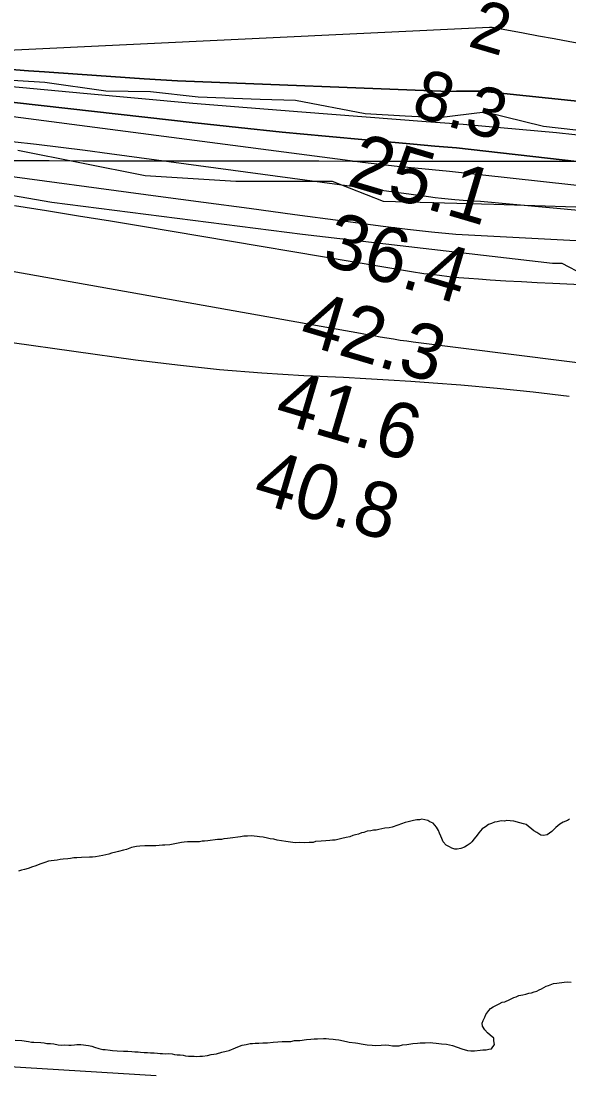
# Model space of a CAD drawing. Extents: x 3219052 to 3256913, y 800770 to 826146.
# Drawn here: x 3234446 to 3235111, y 811124 to 812399 of the extents above; entities that cross this region are included whole.
import ezdxf

# ---------------------------------------------------------------- set-up
doc = ezdxf.new("R2010")
doc.units = 0
for name, color, linetype in [('V-GRID-MAJR', 7, 'Continuous'), ('V-LEVE-TOET', 7, 'Continuous'), ('V-RIVR-EDGE', 7, 'Continuous'), ('V-RIVR-RANG', 7, 'Continuous'), ('V-SITE-VEGE', 7, 'Continuous'), ('V-TOPO-DPTH', 7, 'Continuous'), ('V-TOPO-MAJR', 7, 'Continuous'), ('V-TOPO-MINR', 7, 'Continuous'), ('V-TOPO-SHOR', 7, 'Continuous'), ('V-TOPO-WATR', 7, 'Continuous')]:
    doc.layers.add(name, color=color, linetype=linetype)

msp = doc.modelspace()

# ---------------------------------------------------------------- linework, layer by layer
at = {"layer": 'V-GRID-MAJR'}
msp.add_spline([(3223229.222, 812245.659), (3228465.955, 812237.661), (3233702.6890000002, 812230.425), (3238939.4250000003, 812223.951), (3244176.161, 812218.238), (3249412.899, 812213.287), (3254649.637, 812209.098), (3254649.6380000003, 812209.098)], degree=3, dxfattribs=at)
at = {"layer": 'V-LEVE-TOET'}
msp.add_lwpolyline([(3234610.1010000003, 811119.314), (3234425.474, 811130.638), (3234187.478, 811141.719), (3233931.83, 811153.87), (3233761.803, 811162.105), (3233604.955, 811165.837), (3233406.5160000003, 811173.3470000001), (3233168.7090000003, 811179.556), (3232928.452, 811181.5160000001)], dxfattribs=at)
at = {"layer": 'V-RIVR-EDGE'}
msp.add_lwpolyline([(3234389.041930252, 812329.7287057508), (3234474.661383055, 812324.7355224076), (3234548.96527335, 812314.1194897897), (3234602.86301311, 812313.116857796), (3234661.094620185, 812306.8873591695), (3234736.287210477, 812304.0933543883), (3234778.8822856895, 812302.6839914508), (3234863.604439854, 812286.3913680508), (3234912.281761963, 812283.6629279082), (3234953.1370562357, 812281.8231877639), (3235009.2275255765, 812288.6393591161), (3235080.036806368, 812271.0771006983), (3235140.8753977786, 812264.406476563)], dxfattribs=at)
at = {"layer": 'V-SITE-VEGE'}
for points in [[(3234442.042, 812242.192), (3234596.775, 812211.224), (3234706.808, 812204.34), (3234823.718, 812204.34), (3234885.61, 812180.2540000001), (3235019.714, 812176.811), (3235119.429, 812173.371), (3235301.6720000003, 812152.725), (3235432.3340000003, 812142.4010000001), (3235559.558, 812135.519), (3235648.9590000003, 812111.431), (3235732.2430000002, 812115.209)], [(3235260.409, 812021.964), (3235102.8910000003, 812104.5800000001), (3235091.0130000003, 812104.816), (3234787.737, 812139.888), (3234483.434, 812178.7220000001), (3234217.1350000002, 812224.724)]]:
    msp.add_lwpolyline(points, dxfattribs=at)
at = {"layer": 'V-TOPO-DPTH'}
for points in [[(3236219.5797993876, 812171.8300673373), (3235701.0112393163, 812242.9258117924), (3235694.414456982, 812243.1129452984), (3235660.3686561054, 812245.4549364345), (3235642.6340134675, 812246.8566528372), (3235624.924136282, 812248.4987800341), (3235607.251407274, 812250.501523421), (3235589.6034437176, 812252.7446776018), (3235004.7512205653, 812313.4886094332), (3234994.697642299, 812313.8248193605), (3234984.6384474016, 812313.833251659), (3234974.575508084, 812313.6231655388), (3234965.4019531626, 812313.2819710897), (3234635.619298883, 812326.130380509), (3234595.28107196, 812328.6473075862), (3234554.9512253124, 812331.287867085), (3234514.633949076, 812334.1138752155), (3234474.3250531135, 812337.0635157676), (3234455.097546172, 812338.5149646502), (3234424.4038720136, 812340.7604837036)], [(3234424.4038720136, 812340.7604837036), (3234455.097546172, 812338.5149646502), (3234474.3250531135, 812337.0635157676), (3234514.633949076, 812334.1138752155), (3234554.9512253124, 812331.287867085), (3234595.28107196, 812328.6473075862), (3234635.619298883, 812326.130380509), (3234965.4019531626, 812313.2819710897), (3234974.575508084, 812313.6231655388), (3234984.6384474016, 812313.833251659), (3234994.697642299, 812313.8248193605), (3235004.7512205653, 812313.4886094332), (3235589.6034437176, 812252.7446776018), (3235607.251407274, 812250.501523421), (3235624.924136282, 812248.4987800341), (3235642.6340134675, 812246.8566528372), (3235660.3686561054, 812245.4549364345), (3235694.414456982, 812243.1129452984), (3235701.0112393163, 812242.9258117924), (3236219.5797993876, 812171.8300673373)], [(3237711.6959470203, 812013.2851889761), (3236978.4446943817, 812069.2369252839), (3236972.67980126, 812070.7520773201), (3235637.6560567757, 812168.0903933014), (3235630.8095992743, 812168.954961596), (3235623.973784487, 812169.9111963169), (3235617.340974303, 812170.906967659), (3235607.1922265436, 812172.3974644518), (3235597.0374562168, 812173.8447153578), (3235586.873652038, 812175.2270974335), (3235576.7038252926, 812176.5662336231), (3234974.3108995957, 812244.8412438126), (3234948.2321198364, 812247.113933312), (3234922.1547592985, 812249.4029973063), (3234868.502054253, 812254.1380784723), (3234815.6183309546, 812258.9957155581), (3234762.7598384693, 812264.104991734), (3234709.9391922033, 812269.5917265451), (3234657.143776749, 812275.3301004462), (3234408.9824128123, 812303.2001529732)]]:
    msp.add_lwpolyline(points, dxfattribs=at)
at = {"layer": 'V-TOPO-MAJR'}
msp.add_lwpolyline([(3234402.0279410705, 812214.723163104), (3234612.1876691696, 812186.4229055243), (3234667.5159077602, 812178.9879433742), (3234722.846874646, 812171.5733839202), (3234778.1819339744, 812164.1894285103), (3234833.519721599, 812156.8258757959), (3234885.3669442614, 812149.9413883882), (3234914.810493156, 812146.3028173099), (3234944.2904495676, 812143.0205567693), (3234973.825017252, 812140.2727620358), (3235558.23428724, 812109.4964151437), (3235565.037816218, 812108.1963231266), (3235571.830206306, 812106.8420574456), (3235578.6058880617, 812105.4065312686), (3235585.3704309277, 812103.9168314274), (3236210.408453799, 812045.0384253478)], dxfattribs=at)
at = {"layer": 'V-TOPO-MINR'}
for points in [[(3234430.0256441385, 812363.2484721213), (3235014.625049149, 812391.2791421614), (3235015.10351626, 812391.3047767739), (3235016.9311097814, 812391.3300911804), (3235017.4268970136, 812391.2858917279), (3235017.5909552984, 812391.2598474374), (3235055.2225959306, 812384.4319179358), (3235074.202504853, 812380.9905720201), (3235093.182972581, 812377.5523130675), (3235112.1642785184, 812374.118684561), (3235634.783277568, 812279.7305905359), (3235637.677363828, 812279.3185897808), (3235642.425527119, 812279.2395690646), (3235643.48957829, 812279.4625913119), (3236265.9415057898, 812233.7821427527), (3236282.6928479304, 812233.3282800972), (3236299.492951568, 812233.657322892), (3236328.688809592, 812235.2577443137), (3236330.8262788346, 812235.612818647), (3237034.8478958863, 812152.3173607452), (3237042.4332785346, 812150.4810922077), (3237070.4625623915, 812144.2142284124), (3238468.788826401, 811995.0523872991)], [(3234430.7351166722, 812319.5894952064), (3234521.8584367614, 812311.0818811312), (3234588.0440022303, 812305.0715375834), (3234654.248536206, 812299.284727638), (3234720.4815229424, 812293.8332180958), (3234786.7334781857, 812288.6052421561), (3234937.545494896, 812277.088712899), (3234960.1515100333, 812275.3270871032), (3234982.753703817, 812273.5186181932), (3235005.3501655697, 812271.6398846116), (3235027.942805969, 812269.7143079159), (3235050.5264560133, 812267.68998244), (3235073.1019409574, 812265.5808423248), (3235095.6651782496, 812263.3444802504), (3235118.2202504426, 812261.0233035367), (3235177.6233829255, 812254.7407870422), (3235229.882634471, 812249.3019893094), (3235282.1535355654, 812243.9795257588), (3235334.441910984, 812238.8315634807), (3235386.7419359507, 812233.7999353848), (3235444.531425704, 812228.3375060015), (3235472.3495647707, 812225.6913983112), (3235500.165579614, 812223.0232822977), (3236254.4273411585, 812139.8911612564)], [(3234408.9824128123, 812303.2001529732), (3234657.143776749, 812275.3301004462), (3234709.9391922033, 812269.5917265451), (3234762.7598384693, 812264.104991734), (3234815.6183309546, 812258.9957155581), (3234868.502054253, 812254.1380784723), (3234922.1547592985, 812249.4029973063), (3234948.2321198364, 812247.113933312), (3234974.3108995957, 812244.8412438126), (3235576.7038252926, 812176.5662336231), (3235586.873652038, 812175.2270974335), (3235597.0374562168, 812173.8447153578), (3235607.1922265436, 812172.3974644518), (3235617.340974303, 812170.906967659), (3235623.973784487, 812169.9111963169), (3235630.8095992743, 812168.954961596), (3235637.6560567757, 812168.0903933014), (3236972.67980126, 812070.7520773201), (3236978.4446943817, 812069.2369252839), (3237711.6959470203, 812013.2851889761)], [(3234389.5547021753, 812289.0833983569), (3234839.3901921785, 812230.3752246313), (3234860.4491929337, 812227.7203740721), (3234881.522412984, 812225.188400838), (3234902.6169619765, 812222.8407435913), (3234923.7257302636, 812220.6159636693), (3234944.851145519, 812218.5494723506), (3234965.9845341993, 812216.5711254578), (3235558.795259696, 812151.487020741), (3235587.044893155, 812147.1051769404), (3235615.253882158, 812142.4688761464), (3235643.435774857, 812137.662937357), (3236942.230676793, 812058.3951681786), (3237652.881814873, 811987.293061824)], [(3234434.962991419, 812252.6385372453), (3234464.5223465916, 812249.2440999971), (3234494.0648566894, 812245.7127790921), (3234523.582099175, 812241.9761327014), (3234553.0824965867, 812238.1026026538), (3234940.5309824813, 812185.8580709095), (3234948.4701514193, 812184.853397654), (3234956.4185995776, 812183.9352381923), (3234964.3809665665, 812183.1468494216), (3234972.352612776, 812182.4449744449), (3234987.958356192, 812181.1991342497), (3235003.746365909, 812180.0591836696), (3235545.818580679, 812130.5743479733), (3235562.250964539, 812127.8017561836), (3235578.6617078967, 812124.9101439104), (3236207.163922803, 812094.8384156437), (3236213.1819288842, 812092.9794959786), (3236920.467636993, 812041.1775389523), (3236943.0259246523, 812035.7495556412), (3238400.420479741, 811879.8452404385)], [(3234438.055331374, 812174.9907826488), (3234476.8515582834, 812168.8569196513), (3234515.633267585, 812162.6335782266), (3234554.393200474, 812156.276019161), (3234593.138615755, 812149.8289816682), (3234919.659744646, 812094.9165510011), (3234924.761084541, 812094.0968699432), (3234929.86955215, 812093.3269420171), (3234934.9887113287, 812092.6316437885), (3234940.11499822, 812091.9860986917), (3234953.649429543, 812090.3819703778), (3234965.556697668, 812089.0622577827), (3234977.475182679, 812087.8632320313), (3234989.410493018, 812086.8452365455), (3235001.357020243, 812085.9479279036), (3235015.4173163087, 812084.999109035), (3235034.405919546, 812083.7800412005), (3235053.399203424, 812082.6437476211), (3235072.399508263, 812081.6316154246), (3235091.4044937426, 812080.7022574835), (3235218.983054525, 812074.8814288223)], [(3234368.599802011, 812107.1565972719), (3234858.0144645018, 812020.0166565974), (3234865.9983301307, 812018.6020717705), (3234873.9837667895, 812017.1964563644), (3234881.971559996, 812015.8042950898), (3234889.9609242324, 812014.4211032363), (3234897.9595660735, 812013.098958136), (3234905.969002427, 812011.8492084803), (3234913.9946305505, 812010.7080519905), (3234922.0310531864, 812009.6392909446), (3235285.225404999, 811963.8392559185), (3235322.5443838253, 811959.3574029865), (3235359.894653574, 811955.1704357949)], [(3235111.398821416, 811943.197295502), (3235067.643614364, 811948.6571665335), (3235023.776314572, 811953.1279992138), (3234979.8342862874, 811956.9394729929), (3234946.2612483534, 811959.4700492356), (3234919.0427629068, 811961.4098859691), (3234891.815127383, 811963.2014173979), (3234864.5737667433, 811964.7704908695), (3234837.323256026, 811966.1912590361), (3234789.247706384, 811968.5009455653), (3234738.016922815, 811971.6556376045), (3234686.871815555, 811975.7292158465), (3234635.8552227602, 811981.1811233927), (3234584.9243062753, 811987.5519171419), (3234359.9949945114, 812018.7758344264)]]:
    msp.add_lwpolyline(points, dxfattribs=at)
at = {"layer": 'V-TOPO-SHOR'}
for points in [[(3235111.613, 811430.702), (3235109.0700000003, 811428.937), (3235103.954, 811427.122), (3235099.71, 811424.464), (3235095.0640000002, 811420.514), (3235092.108, 811417.882), (3235090.003, 811415.6950000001), (3235084.498, 811411.726), (3235080.222, 811410.786), (3235076.779, 811411.15), (3235071.995, 811414.4940000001), (3235068.519, 811416.573), (3235065.904, 811418.67), (3235061.548, 811422.023), (3235058.933, 811424.12), (3235055.912, 811424.921), (3235051.167, 811426.1190000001), (3235044.259, 811428.134), (3235039.5300000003, 811428.4720000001), (3235035.659, 811428.828), (3235032.663, 811428.343), (3235028.792, 811428.697), (3235023.666, 811427.313), (3235020.6720000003, 811426.828), (3235016.832, 811425.466), (3235013.424, 811424.1140000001), (3235009.611, 811421.466), (3235005.7970000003, 811418.816), (3235003.6920000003, 811416.631), (3235001.595, 811414.013), (3234999.498, 811411.398), (3234995.725, 811406.604), (3234993.217, 811403.122), (3234991.111, 811400.935), (3234987.29, 811398.7170000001), (3234984.326, 811396.513), (3234979.628, 811395.135), (3234975.3540000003, 811394.197), (3234972.349, 811394.137), (3234968.892, 811395.36), (3234965.855, 811397.0210000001), (3234961.952, 811399.093), (3234958.437, 811403.319), (3234956.647, 811407.148), (3234955.304, 811410.128), (3234953.95, 811413.536), (3234952.596, 811416.946), (3234950.378, 811420.767), (3234945.988, 811425.836), (3234942.092, 811427.479), (3234939.485, 811429.148), (3234936.036, 811429.9400000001), (3234932.585, 811430.733), (3234929.597, 811429.818), (3234926.165, 811429.752), (3234922.319, 811428.8200000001), (3234915.907, 811427.411), (3234912.06, 811426.479), (3234907.792, 811425.109), (3234903.105, 811423.305), (3234896.279, 811421.028), (3234892.862, 811420.104), (3234887.292, 811419.567), (3234880.019, 811418.142), (3234877.031, 811417.226), (3234873.599, 811417.161), (3234870.603, 811416.676), (3234865.89, 811416.155), (3234862.061, 811414.365), (3234859.0640000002, 811413.88), (3234855.654, 811412.5260000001), (3234851.808, 811411.594), (3234848.8200000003, 811410.679), (3234844.982, 811409.319), (3234840.708, 811408.3790000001), (3234835.154, 811406.986), (3234832.1580000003, 811406.4990000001), (3234827.032, 811405.115), (3234824.0270000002, 811405.057), (3234820.603, 811404.562), (3234815.88, 811404.474), (3234810.31, 811403.937), (3234803.453, 811403.378), (3234800.465, 811402.462), (3234795.742, 811402.372), (3234790.1720000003, 811401.838)], [(3234790.1720000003, 811401.838), (3234783.727, 811402.145), (3234779.006, 811402.055), (3234775.9930000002, 811402.426), (3234772.981, 811402.7980000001), (3234767.386, 811403.552), (3234756.623, 811405.063), (3234752.736, 811406.278), (3234748.437, 811406.6240000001), (3234744.989, 811407.419), (3234739.813, 811408.608), (3234735.504, 811409.385), (3234732.494, 811409.755), (3234729.051, 811410.12), (3234725.61, 811410.484), (3234720.898, 811409.964), (3234716.177, 811409.8740000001), (3234712.321, 811409.372), (3234699.9080000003, 811407.421), (3234696.4760000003, 811407.353), (3234692.193, 811406.843), (3234689.205, 811405.9280000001), (3234684.485, 811405.838), (3234672.492, 811404.322), (3234668.637, 811403.8200000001), (3234665.633, 811403.763), (3234662.637, 811403.2760000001), (3234658.774, 811403.204), (3234651.4790000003, 811403.0650000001), (3234648.0470000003, 811402.9990000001), (3234643.754, 811402.917), (3234640.758, 811402.432), (3234634.773, 811401.029), (3234626.645, 811399.587), (3234620.644, 811399.042), (3234617.64, 811398.987), (3234609.495, 811398.4010000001), (3234603.486, 811398.289), (3234599.196, 811398.207), (3234596.1890000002, 811398.149), (3234590.182, 811398.035), (3234585.9, 811397.525), (3234579.916, 811396.1240000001), (3234573.948, 811393.863), (3234570.102, 811392.931), (3234564.117, 811391.528), (3234561.129, 811390.615), (3234555.575, 811389.22), (3234552.5870000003, 811388.305), (3234548.741, 811387.373), (3234545.323, 811386.449), (3234536.336, 811384.991), (3234532.482, 811384.487), (3234529.048, 811384.422), (3234519.178, 811384.235), (3234513.608, 811383.701), (3234510.173, 811383.633), (3234505.8910000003, 811383.123), (3234502.895, 811382.638), (3234496.894, 811382.093), (3234493.47, 811381.599), (3234489.613, 811381.098), (3234482.335, 811380.1), (3234479.338, 811379.615), (3234474.642, 811378.237), (3234469.955, 811376.43), (3234462.7090000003, 811373.7170000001), (3234459.721, 811372.801), (3234454.603, 811370.987), (3234449.907, 811369.608), (3234446.489, 811368.685), (3234442.642, 811367.755)], [(3234682.983, 811146.071), (3234689.818, 811147.919), (3234694.9420000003, 811149.305), (3234698.36, 811150.229), (3234706.028, 811153.3790000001), (3234711.143, 811155.193), (3234714.123, 811156.539), (3234719.258, 811157.495), (3234723.9620000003, 811158.443), (3234726.966, 811158.501), (3234729.9620000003, 811158.986), (3234734.683, 811159.076), (3234739.404, 811159.166), (3234744.983, 811159.273), (3234751.833, 811160.26), (3234757.412, 811160.366), (3234762.982, 811160.903), (3234770.279, 811161.04), (3234773.284, 811161.0970000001), (3234777.988, 811162.046), (3234780.9930000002, 811162.103), (3234784.4250000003, 811162.169), (3234792.5640000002, 811163.18), (3234797.704, 811163.709), (3234801.559, 811164.21), (3234805.8510000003, 811164.292), (3234813.146, 811164.432), (3234816.151, 811164.4890000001), (3234819.591, 811164.1240000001), (3234824.75, 811163.7930000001), (3234827.7630000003, 811163.422), (3234831.633, 811163.066), (3234841.116, 811161.1), (3234844.136, 811160.299), (3234851.886, 811159.158), (3234854.899, 811158.785), (3234858.778, 811158.001), (3234866.097, 811156.8520000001), (3234872.112, 811156.537), (3234876.413, 811156.188), (3234882.852, 811156.311), (3234888.85, 811156.854), (3234892.291, 811156.492), (3234896.6, 811155.713), (3234904.753, 811155.8690000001), (3234909.029, 811156.809), (3234914.1720000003, 811157.335), (3234921.45, 811158.333), (3234927.021, 811158.8690000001), (3234930.447, 811159.363), (3234933.452, 811159.42), (3234936.454, 811159.4770000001), (3234942.465, 811159.59), (3234945.906, 811159.228), (3234949.776, 811158.871), (3234956.23, 811158.136), (3234962.247, 811157.821), (3234966.126, 811157.036), (3234969.574, 811156.2440000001), (3234975.194, 811154.204), (3234980.8140000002, 811152.164), (3234987.722, 811150.149), (3234992.02, 811149.801), (3234996.321, 811149.453), (3235003.1720000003, 811150.442), (3235006.596, 811150.935), (3235010.4590000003, 811151.009), (3235013.8850000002, 811151.505), (3235016.879, 811151.99), (3235020.645, 811157.214), (3235019.697, 811161.919), (3235019.64, 811164.9230000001), (3235015.276, 811168.704), (3235012.214, 811171.6510000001), (3235008.716, 811175.02), (3235006.049, 811179.689), (3235005.556, 811183.116), (3235006.778, 811186.573), (3235008.8510000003, 811190.476), (3235010.082, 811193.505), (3235013.846, 811198.729), (3235015.949, 811200.915), (3235018.913, 811203.118), (3235026.144, 811206.6900000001), (3235029.974, 811208.48), (3235032.97, 811208.9670000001), (3235039.35, 811212.093), (3235044.029, 811214.329), (3235047.017, 811215.245), (3235049.997, 811216.588), (3235055.132, 811217.544), (3235058.548, 811218.468), (3235062.394, 811219.4), (3235065.39, 811219.887), (3235068.8000000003, 811221.2390000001), (3235071.788, 811222.154), (3235074.768, 811223.5), (3235077.7460000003, 811224.844), (3235080.289, 811226.611), (3235083.267, 811227.954), (3235086.255, 811228.87)], [(3235086.255, 811228.87), (3235092.225, 811231.131), (3235096.077, 811231.633), (3235105.066, 811233.091), (3235109.787, 811233.181), (3235113.657, 811232.8250000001)], [(3234438.819, 811162.468), (3234446.98, 811162.191), (3234455.16, 811161.061), (3234458.609, 811160.268), (3234461.613, 811160.323), (3234469.7830000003, 811159.621), (3234474.083, 811159.273), (3234477.102, 811158.4720000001), (3234481.825, 811158.562), (3234485.6950000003, 811158.206), (3234490.869, 811157.0160000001), (3234494.739, 811156.661), (3234498.602, 811156.733), (3234503.761, 811156.403), (3234506.765, 811156.461), (3234510.62, 811156.963), (3234513.616, 811157.4500000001), (3234518.345, 811157.11), (3234527.811, 811156), (3234531.6890000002, 811155.216), (3234535.146, 811153.995), (3234540.33, 811152.375), (3234545.073, 811151.179), (3234548.08, 811151.234), (3234554.103, 811150.491), (3234557.115, 811150.118), (3234562.702, 811149.797), (3234570.444, 811149.084), (3234575.594, 811149.182), (3234580.323, 811148.8420000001), (3234584.194, 811148.488), (3234588.057, 811148.56), (3234591.0670000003, 811148.189), (3234595.376, 811147.4130000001), (3234599.239, 811147.484), (3234603.109, 811147.128), (3234607.4020000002, 811147.212), (3234611.701, 811146.8640000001), (3234614.713, 811146.491), (3234617.718, 811146.5480000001), (3234620.73, 811146.176), (3234624.593, 811146.2490000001), (3234629.322, 811145.909), (3234632.34, 811145.109), (3234635.353, 811144.736), (3234639.216, 811144.812), (3234642.6580000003, 811144.447), (3234645.677, 811143.644), (3234649.12, 811143.282), (3234655.995, 811142.983), (3234659.436, 811142.618), (3234662.862, 811143.1140000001), (3234666.294, 811143.18), (3234672.287, 811144.15), (3234676.563, 811145.09), (3234682.983, 811146.071)]]:
    msp.add_lwpolyline(points, dxfattribs=at)
at = {"layer": 'V-TOPO-WATR'}
msp.add_lwpolyline([(3234424.4038720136, 812340.7604837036), (3234455.097546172, 812338.5149646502), (3234474.3250531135, 812337.0635157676), (3234514.633949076, 812334.1138752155), (3234554.9512253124, 812331.287867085), (3234595.28107196, 812328.6473075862), (3234635.619298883, 812326.130380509), (3234965.4019531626, 812313.2819710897), (3234974.575508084, 812313.6231655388), (3234984.6384474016, 812313.833251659), (3234994.697642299, 812313.8248193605), (3235004.7512205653, 812313.4886094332), (3235589.6034437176, 812252.7446776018), (3235607.251407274, 812250.501523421), (3235624.924136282, 812248.4987800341), (3235642.6340134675, 812246.8566528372), (3235660.3686561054, 812245.4549364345), (3235694.414456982, 812243.1129452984), (3235701.0112393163, 812242.9258117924), (3236219.5797993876, 812171.8300673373)], dxfattribs=at)

# ---------------------------------------------------------------- texts
at = {"layer": 'V-RIVR-RANG'}
for s, height, rotation, p in [('2', 60, 343.58866666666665, (3234986.7182126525, 812368.6950033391)), ('8.3', 60, 343.58866666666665, (3234917.791860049, 812284.7491412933)), ('25.1', 67, 343.5183257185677, (3234839.845794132, 812199.9594095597)), ('36.4', 67, 343.5183257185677, (3234809.430325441, 812104.6739383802)), ('42.3', 67, 343.5183257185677, (3234781.291325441, 812008.7149383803)), ('41.6', 67, 343.5183257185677, (3234751.381738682, 811913.2787941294)), ('40.8', 67, 343.5183257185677, (3234725.014325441, 811816.7959383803))]:
    msp.add_text(s, height=height, rotation=rotation, dxfattribs=at).set_placement(p)

doc.saveas('drawing.dxf')
